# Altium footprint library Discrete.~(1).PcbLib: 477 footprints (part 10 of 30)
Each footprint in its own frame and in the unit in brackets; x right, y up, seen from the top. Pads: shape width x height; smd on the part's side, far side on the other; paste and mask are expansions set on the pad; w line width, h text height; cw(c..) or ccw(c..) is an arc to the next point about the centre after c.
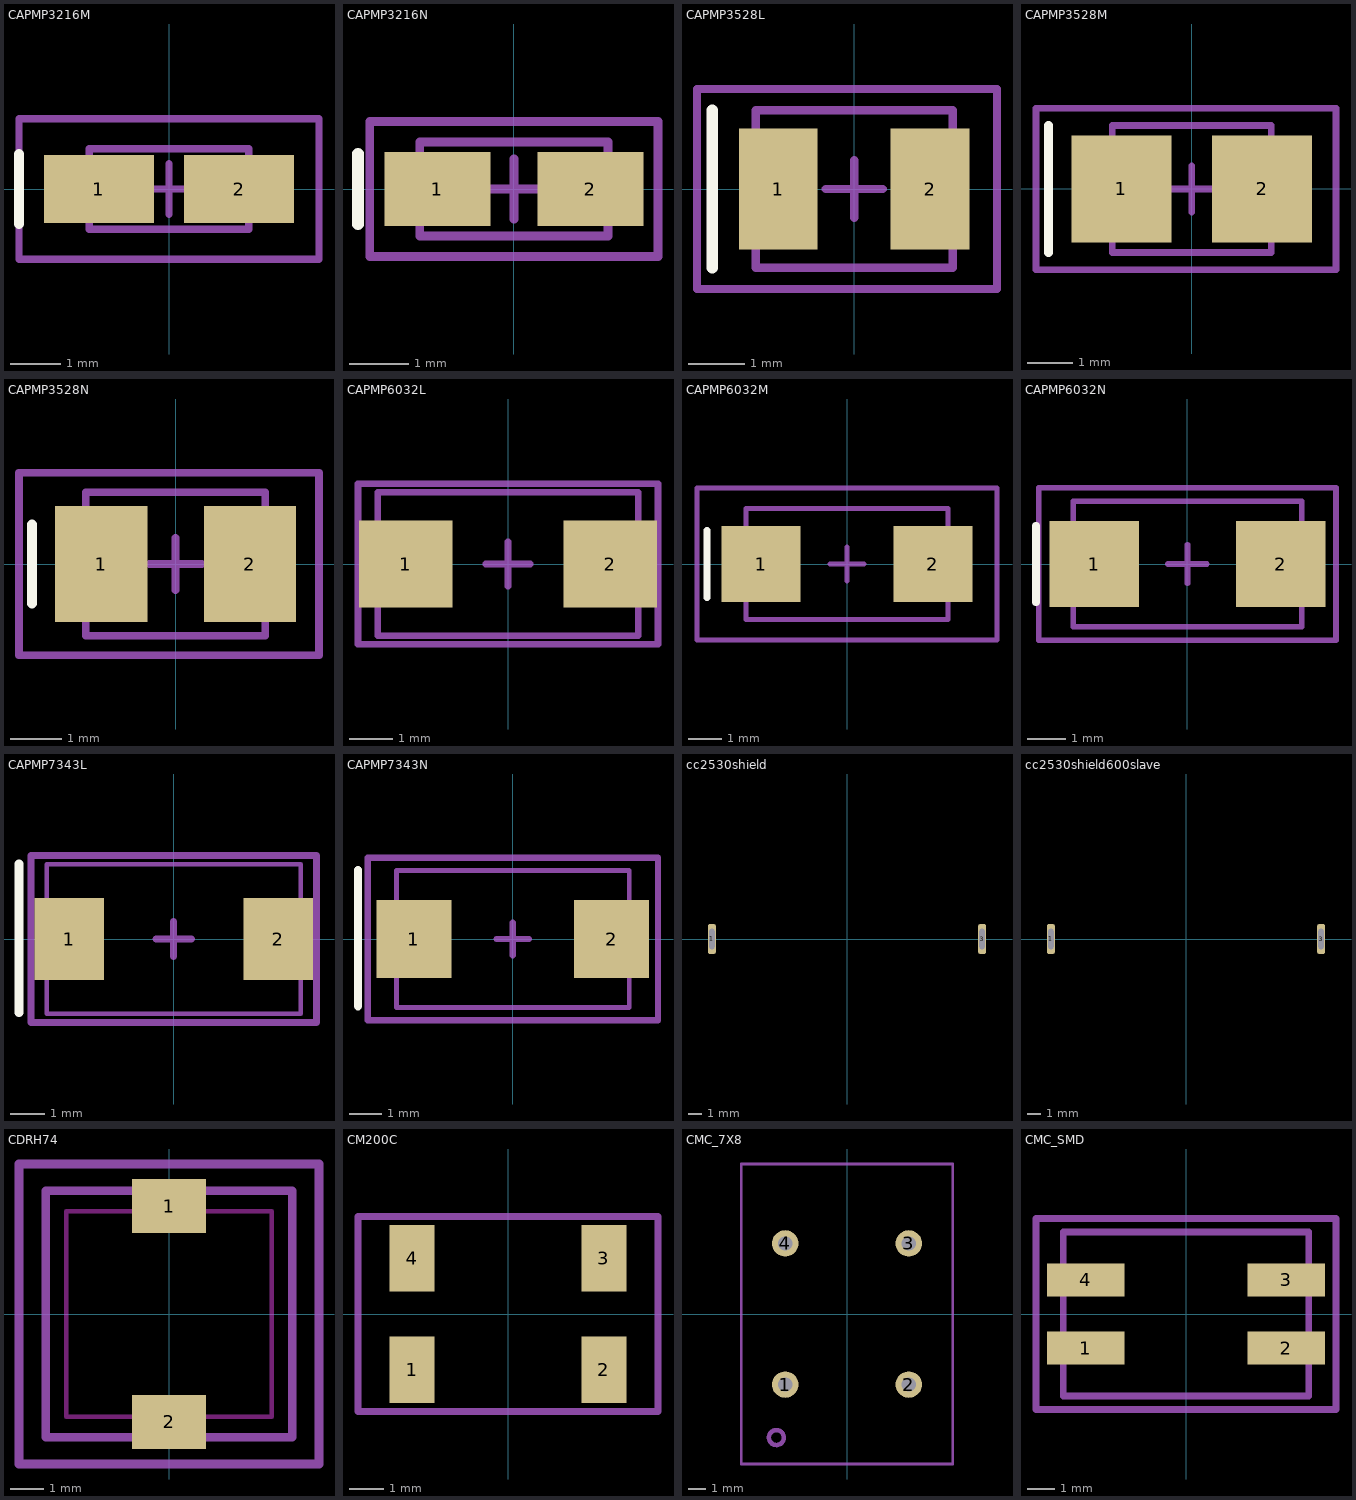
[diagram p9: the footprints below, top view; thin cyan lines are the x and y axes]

## CAPMP3216M [mm] "Capacitor, polarized, Molded, CASE A"
height 1.8
pads (2):
  rect 2.2x1.35 smd: 1(-1.4,0) 2(1.4,0)
Top Overlay:
  lines w0.2: -3,-0.7 -3,0.7
Mechanical 13:
  lines w0.15: -1.6,-0.8 1.6,-0.8 1.6,0.8 -1.6,0.8 -1.6,-0.8
Mechanical 15:
  lines w0.15: -0.508,0 0.508,0 ; 0,-0.508 0,0.508 ; -3,-1.4 -3,1.4 3,1.4 3,-1.4 -3,-1.4
3D body "CD A(3216).STEP": height 1.6, standoff -0.01, extent -1.6,-0.8 1.6,0.8

## CAPMP3216N [mm] "Capacitor, polarized, Molded, CASE A"
height 1.8
pads (2):
  rect 1.8x1.25 smd: 1(-1.3,0) 2(1.3,0)
Top Overlay:
  lines w0.2: -2.65,-0.6 -2.65,0.6
Mechanical 13:
  lines w0.15: -1.6,-0.8 1.6,-0.8 1.6,0.8 -1.6,0.8 -1.6,-0.8
Mechanical 15:
  lines w0.15: -0.508,0 0.508,0 ; 0,-0.508 0,0.508 ; -2.45,-1.15 2.45,-1.15 2.45,1.15 -2.45,1.15 -2.45,-1.15
3D body "CD A(3216).STEP": height 1.6, standoff -0.01, extent -1.6,-0.8 1.6,0.8

## CAPMP3528L [mm] "Capacitor, polarized, Molded, CASE B"
height 2.1
pads (2):
  rect 1.4x2.15 smd: 1(-1.35,0) 2(1.35,0)
Top Overlay:
  lines w0.2: -2.523,-1.4 -2.523,1.4
Mechanical 13:
  lines w0.15: -1.75,-1.4 1.75,-1.4 1.75,1.4 -1.75,1.4 -1.75,-1.4
Mechanical 15:
  lines w0.15: -0.508,0 0.508,0 ; 0,-0.508 0,0.508 ; -2.794,-1.778 -2.794,1.778 2.54,1.778 2.54,-1.778 -2.794,-1.778
3D body "CD B(3528).STEP": height 1.9, standoff -0.01, extent -1.75,-1.4 1.75,1.4

## CAPMP3528M [mm] "Capacitor, polarized, Molded, CASE B"
height 2.1
pads (2):
  rect 2.2x2.35 smd: 1(-1.55,0) 2(1.55,0)
Top Overlay:
  lines w0.2: -3.158,-1.4 -3.158,1.4
Mechanical 13:
  lines w0.15: -1.75,-1.4 1.75,-1.4 1.75,1.4 -1.75,1.4 -1.75,-1.4
Mechanical 15:
  lines w0.15: -0.508,0 0.508,0 ; 0,-0.508 0,0.508 ; -3.429,-1.778 -3.429,1.778 3.175,1.778 3.175,-1.778 -3.429,-1.778
3D body "CD B(3528).STEP": height 1.9, standoff -0.01, extent -1.75,-1.4 1.75,1.4

## CAPMP3528N [mm] "Capacitor, polarized, Molded, CASE B"
height 2.1
pads (2):
  rect 1.8x2.25 smd: 1(-1.45,0) 2(1.45,0)
Top Overlay:
  lines w0.2: -2.794,-0.762 -2.794,0.762
Mechanical 13:
  lines w0.15: -1.75,-1.4 1.75,-1.4 1.75,1.4 -1.75,1.4 -1.75,-1.4
Mechanical 15:
  lines w0.15: -0.508,0 0.508,0 ; 0,-0.508 0,0.508 ; -3.048,-1.778 -3.048,1.778 2.794,1.778 2.794,-1.778 -3.048,-1.778
3D body "CD B(3528).STEP": height 1.9, standoff -0.01, extent -1.75,-1.4 1.75,1.4

## CAPMP6032L [mm] "Capacitor, polarized, Molded, CASE C"
height 2.8
pads (2):
  rect 2.15x2 smd: 1(-2.35,0) 2(2.35,0)
Mechanical 13:
  lines w0.15: -3,-1.65 3,-1.65 3,1.65 -3,1.65 -3,-1.65
Mechanical 15:
  lines w0.15: -0.508,0 0.508,0 ; 0,-0.508 0,0.508 ; -3.45,-1.85 3.45,-1.85 3.45,1.85 -3.45,1.85 -3.45,-1.85
3D body "CD C(6032).STEP": height 2.5, standoff -0.01, extent -3,-1.6 3,1.6

## CAPMP6032M [mm] "Capacitor, polarized, Molded, CASE C"
height 2.8
pads (2):
  rect 2.35x2.25 smd: 1(-2.55,0) 2(2.55,0)
Top Overlay:
  lines w0.2: -4.15,-1 -4.15,1
Mechanical 13:
  lines w0.15: -3,-1.65 3,-1.65 3,1.65 -3,1.65 -3,-1.65
Mechanical 15:
  lines w0.15: -0.508,0 0.508,0 ; 0,-0.508 0,0.508 ; -4.45,-2.25 -4.45,2.25 4.45,2.25 4.45,-2.25 -4.45,-2.25
3D body "CD C(6032).STEP": height 2.5, standoff -0.01, extent -3,-1.6 3,1.6

## CAPMP6032N [mm] "Capacitor, polarized, Molded, CASE C"
height 2.8
pads (2):
  rect 2.35x2.25 smd: 1(-2.45,0) 2(2.45,0)
Top Overlay:
  lines w0.2: -3.975,-1 -3.975,1
Mechanical 13:
  lines w0.15: -3,-1.65 -3,1.65 3,1.65 3,-1.65 -3,-1.65
Mechanical 15:
  lines w0.15: -0.508,0 0.508,0 ; 0,-0.508 0,0.508 ; -3.9,-2 -3.9,2 3.9,2 3.9,-2 -3.9,-2
3D body "CD C(6032).STEP": height 2.5, standoff -0.01, extent -3,-1.6 3,1.6

## CAPMP7343L [mm]
pads (2):
  rect 2x2.35 smd: 1(-3,0) 2(3,0)
Top Overlay:
  lines w0.254: -4.445,-2.108 -4.445,2.159
Mechanical 13:
  lines w0.127: -3.65,-2.15 3.65,-2.15 3.65,2.15 -3.65,2.15 -3.65,-2.15
Mechanical 15:
  lines w0.2: -0.508,0 0.508,0 ; 0,-0.508 0,0.508 ; -4.1,-2.4 -4.1,2.4 4.1,2.4 4.1,-2.4 -4.1,-2.4
3D body "CD E(7343H).STEP": height 4, standoff -0.01, extent -3.65,-2.15 3.65,2.15

## CAPMP7343N [mm]
pads (2):
  rect 2.35x2.45 smd: 1(-3.1,0) 2(3.1,0)
Top Overlay:
  lines w0.254: -4.851,-2.108 -4.851,2.159
Mechanical 13:
  lines w0.152: -3.65,-2.15 -3.65,2.15 3.65,2.15 3.65,-2.15 -3.65,-2.15
Mechanical 15:
  lines w0.2: -0.508,0 0.508,0 ; 0,-0.508 0,0.508 ; -4.55,-2.55 -4.55,2.55 4.55,2.55 4.55,-2.55 -4.55,-2.55
3D body "CD E(7343H).STEP": height 4, standoff -0.01, extent -3.65,-2.15 3.65,2.15

## cc2530shield [mm]
pads (2):
  rrect50% 0.6x2.2 hole 0.4 slot 1.5 at 90 deg: 1(-10,0) 3(10,0)
Top Solder:
  lines w0.8: -3.4,10.5 -10,10.5 -10,-10.5 10,-10.5 10,10.5 -0.4,10.5
3D body: height 2.5, standoff 2.2, extent -10,-10.5 10,10.5
3D body: height 2.2, standoff 0, extent -10,-10.5 -9.8,10.5
3D body: height 2.2, standoff 0, extent -10,-10.5 10,-10.3
3D body: height 2.2, standoff 0, extent 9.8,-10.5 10,10.5
3D body: height 2.2, standoff 0, extent -10,10.3 10,10.5

## cc2530shield600slave [mm]
pads (2):
  rrect50% 0.6x2.2 hole 0.4 slot 1.5 at 90 deg: 1(-10,0) 3(10,0)
Top Solder:
  lines w0.8: 3.556,10.5 -10,10.5 -10,-10.5 10,-10.5 10,10.5 5.588,10.5
3D body: height 2.5, standoff 2.2, extent -10,-10.5 10,10.5
3D body: height 2.2, standoff 0, extent -10,-10.5 -9.8,10.5
3D body: height 2.2, standoff 0, extent -10,-10.5 10,-10.3
3D body: height 2.2, standoff 0, extent 9.8,-10.5 10,10.5
3D body: height 2.2, standoff 0, extent -10,10.3 10,10.5

## CDRH74 [mm] "SMD Power Inductor 7.5x7.5x4.5mm"
height 4.5
pads (2):
  rect 2.2x1.6 smd: 1(0,3.2) 2(0,-3.2)
Keep-Out Layer:
  lines w0.127: -3.048,-3.048 -3.048,3.048 3.048,3.048 3.048,-3.048 -3.048,-3.048
Mechanical 13:
  lines w0.254: -3.65,-3.65 -3.65,3.65 3.65,3.65 3.65,-3.65 -3.65,-3.65
Mechanical 15:
  lines w0.254: -4.445,-4.445 4.445,-4.445 4.445,4.445 -4.445,4.445 -4.445,-4.445
3D body "CDRH74.STEP": height 4.5, standoff 0, extent -3.65,-3.65 3.65,3.65

## CM200C [mm] "CITIZEN 4-PIN CRYSTAL"
pads (4):
  rect 1.3x1.9 smd: 1(-2.75,-1.6) 2(2.75,-1.6) 3(2.75,1.6) 4(-2.75,1.6)
Mechanical 15:
  lines w0.2: -4.3,-2.8 -4.3,2.8 4.3,2.8 4.3,-2.8 -4.3,-2.8
3D body: height 2.4, standoff 0, extent -4,-1.9 4,1.9

## CMC_7X8 [mm]
pads (4):
  round 1.5 hole 0.8: 1(-3.5,-4) 2(3.5,-4) 3(3.5,4) 4(-3.5,4)
Mechanical 13:
  circle w0.254: c-4,-7 r0.424
  lines w0.152: -6,-8.5 -6,8.5 6,8.5 6,-8.5 -6,-8.5
3D body "UU9.8.STEP": height 17.05, standoff -3.45, extent -6,-8.5 6,8.5

## CMC_SMD [mm]
pads (4):
  rect 2.85x1.2 smd: 1(-3.675,-1.25) 2(3.675,-1.25) 3(3.675,1.25) 4(-3.675,1.25)
Mechanical 13:
  lines w0.254: -4.5,-3 -4.5,3 4.5,3 4.5,-3 -4.5,-3
Mechanical 15:
  lines w0.254: -5.5,-3.5 5.5,-3.5 5.5,3.5 -5.5,3.5 -5.5,-3.5
3D body "User Library-EPCOS B82790-S513-N201.STEP": height 4.9, standoff -0.25, extent -4.5,-3 4.5,3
